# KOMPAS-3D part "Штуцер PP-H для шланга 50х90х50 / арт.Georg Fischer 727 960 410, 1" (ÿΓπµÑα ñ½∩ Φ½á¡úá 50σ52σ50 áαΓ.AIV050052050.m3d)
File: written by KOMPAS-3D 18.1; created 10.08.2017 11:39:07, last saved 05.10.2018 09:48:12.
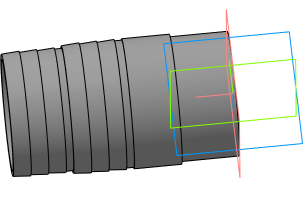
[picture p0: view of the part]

Document properties: Автор: Мирончук; Организация: Мирончук; Полное имя файла: D:\Мембранные насосы\Мембранный электропривод\А302-00.00.000 - ASTRA-302 (МЭ200)\3Д ПВХ\Отработка\Штуцер для шланга 50х52х50 арт.AIV050052050.m3d

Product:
- Part/product: Штуцер PP-H для шланга 50х90х50 / арт.Georg Fischer 727 960 410  | designation 1
    Масса: 0.0344906
    Раздел спецификации: Прочие изделия
- Part/product: Штуцер ПВХ для шланга 50х52х50 / арт.AIV050052050
    Масса: 0.0416933
    Раздел спецификации: Прочие изделия

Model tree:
1. Эскиз:1
2. Операция вращения:1  (labels: D4; d1; d1L)
     Угол 1 = 360

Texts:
  Линейный размер с обрывом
